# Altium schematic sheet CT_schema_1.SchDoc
size 542 x 264 mm
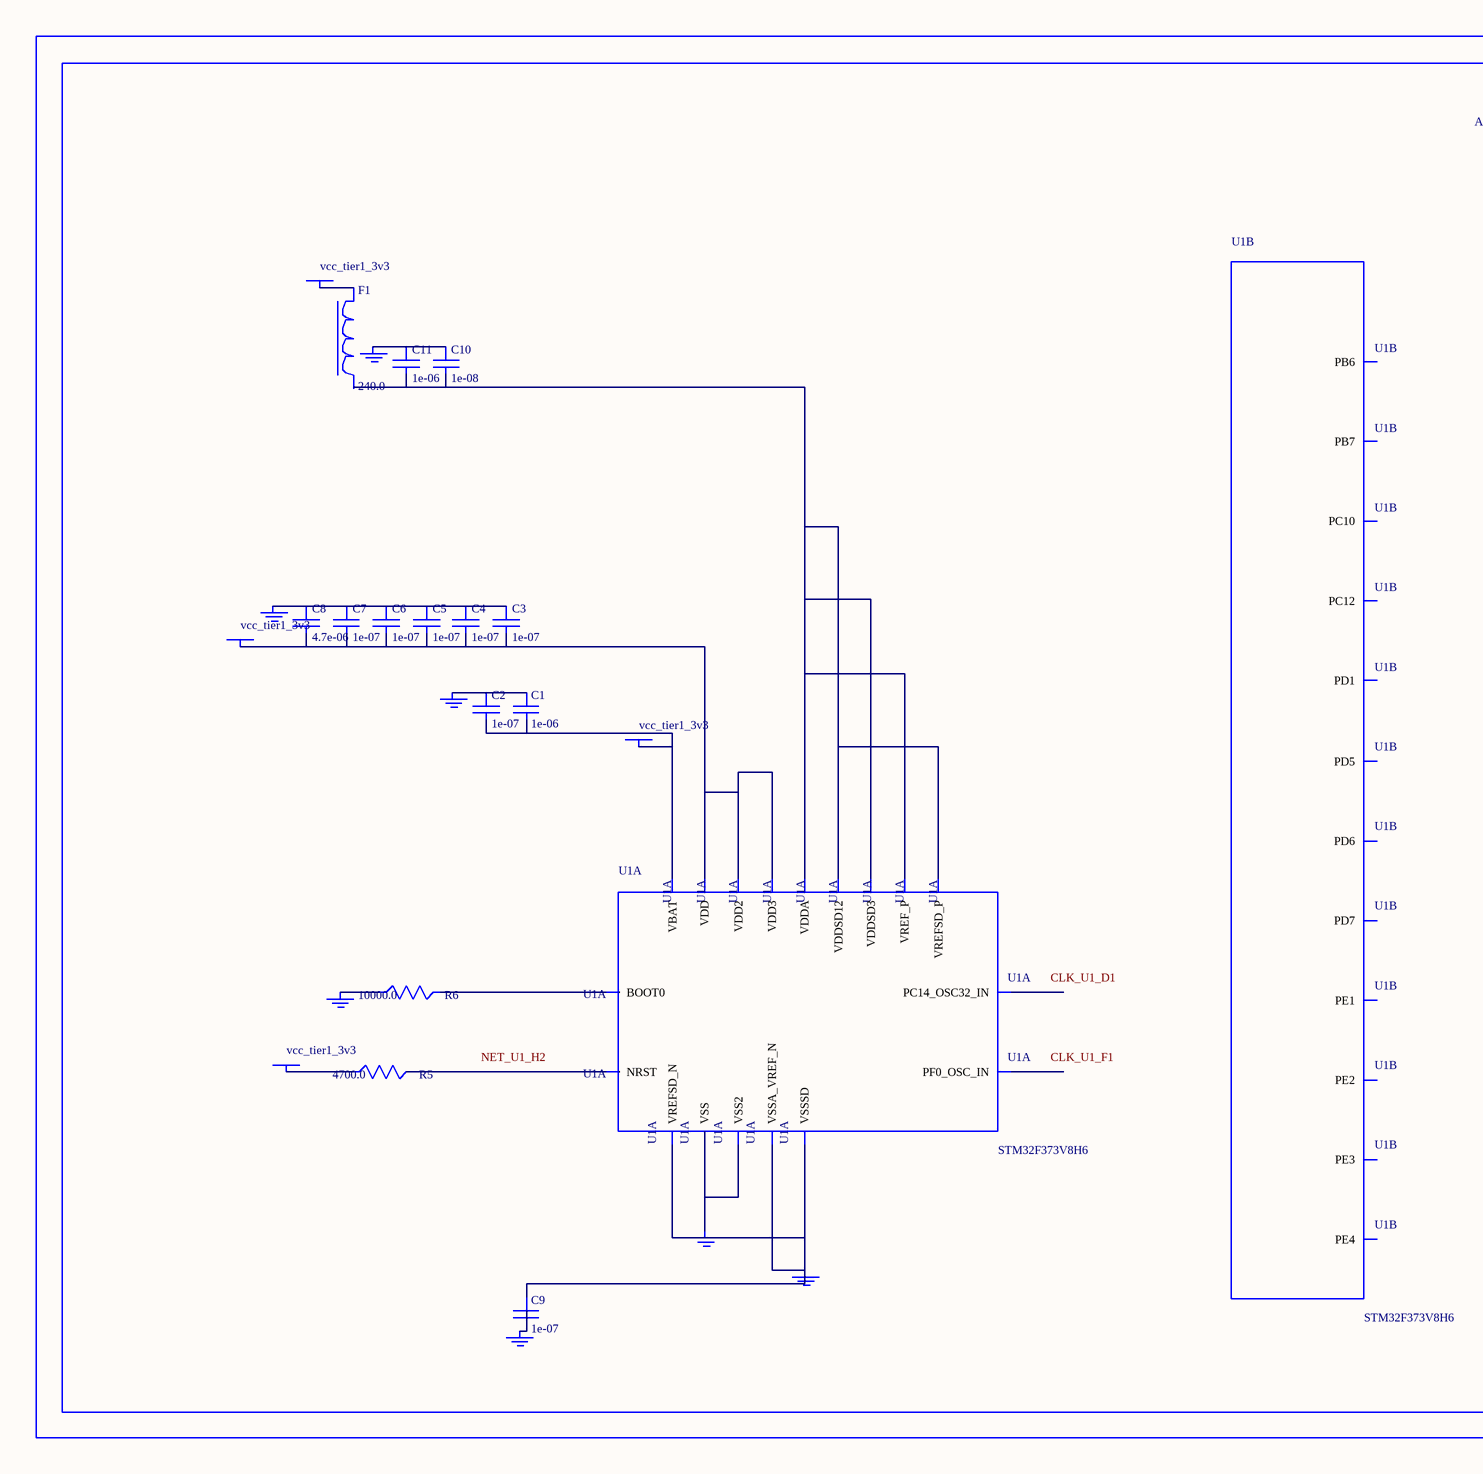
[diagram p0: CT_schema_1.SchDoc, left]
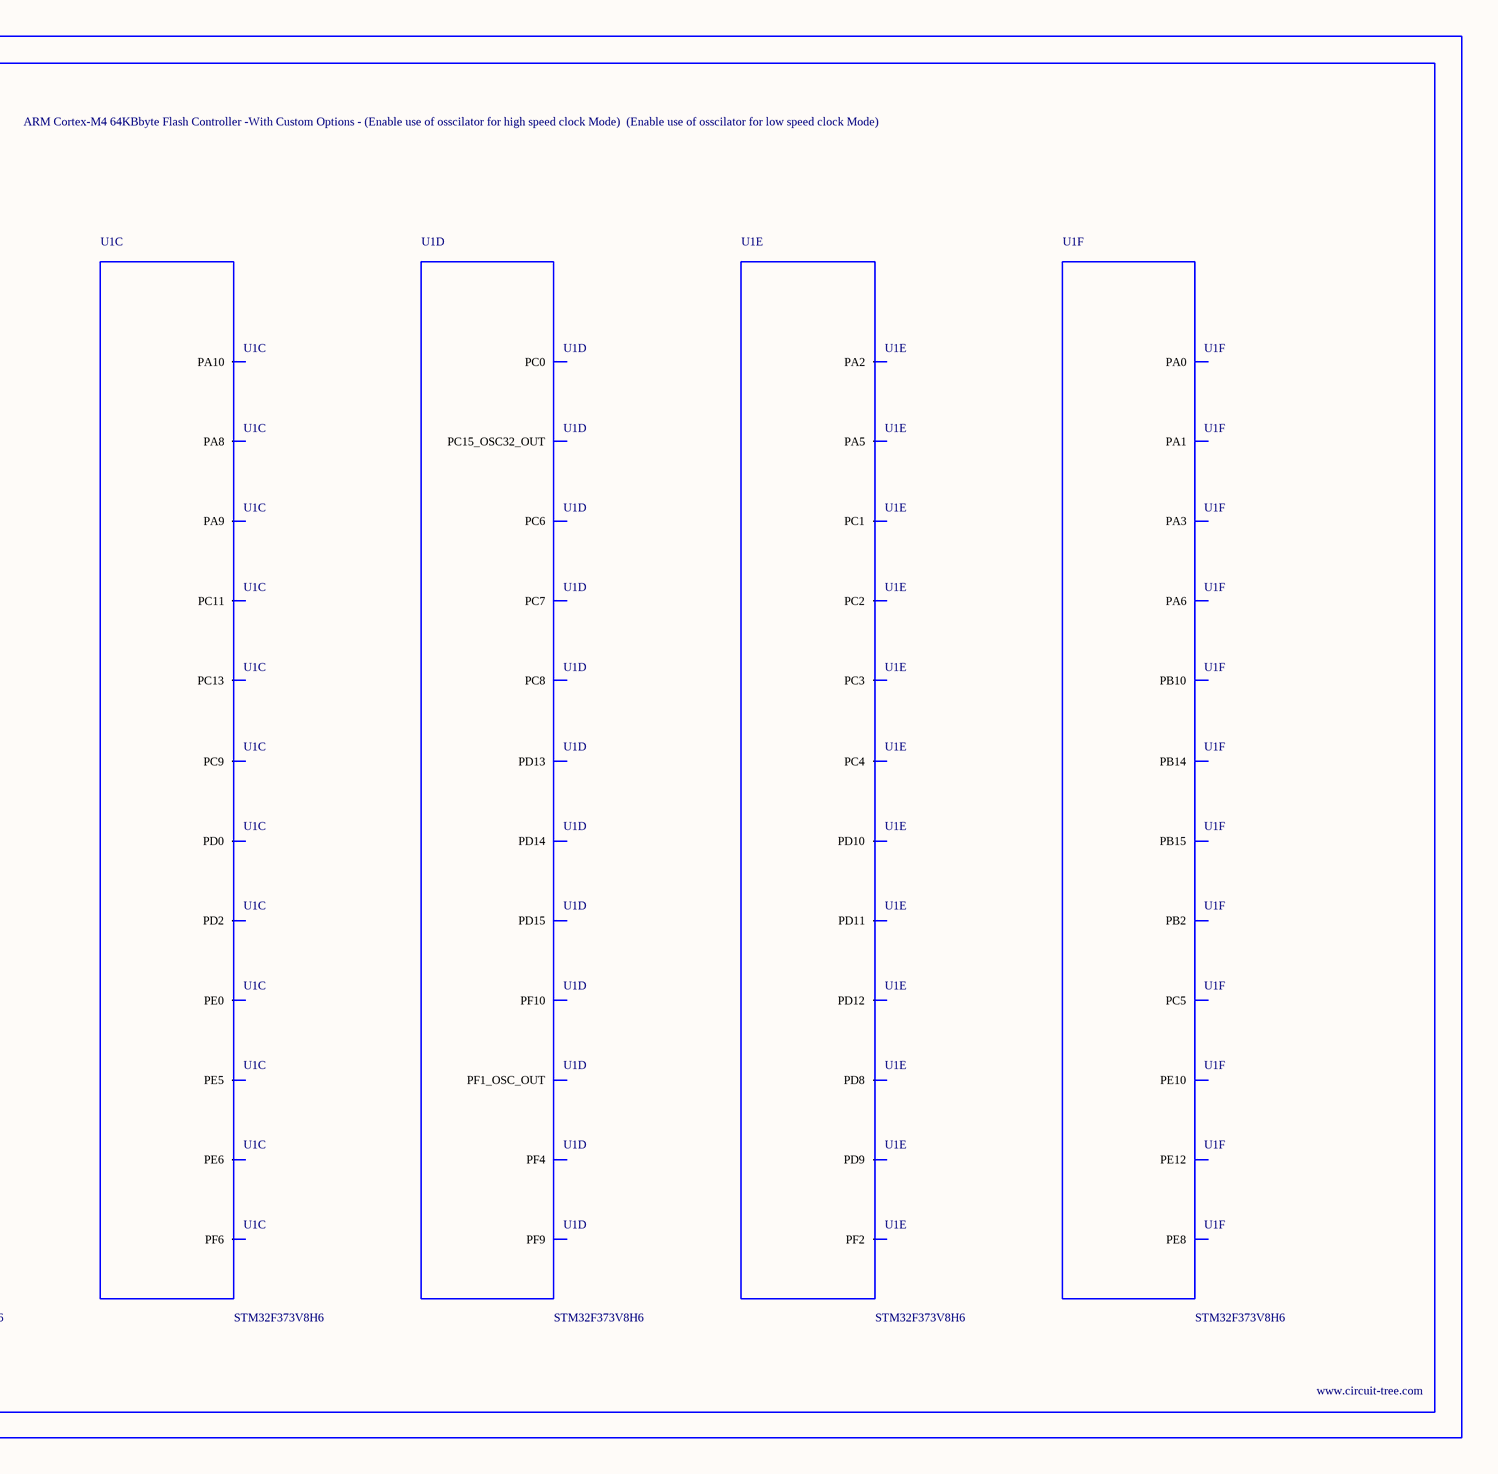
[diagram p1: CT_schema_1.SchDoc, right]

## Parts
BORDER0  (no value)
C1  1e-06  [C0603]
C2  1e-07  [C0603]
C3  1e-07  [C0603]
C4  1e-07  [C0603]
C5  1e-07  [C0603]
C6  1e-07  [C0603]
C7  1e-07  [C0603]
C8  4.7e-06  [C0603]
C9  1e-07  [C0603]
C10  1e-08  [C0603]
C11  1e-06  [C0603]
F1  240.0  [L0603]
GND_INSTANCE_0_0  (no value)
GND_INSTANCE_0_1  (no value)
GND_INSTANCE_0_2  (no value)
GND_INSTANCE_0_3  (no value)
GND_INSTANCE_0_4  (no value)
GND_INSTANCE_0_5  (no value)
GND_INSTANCE_0_6  (no value)
POWER_INSTANCE_0_0  vcc_tier1_3v3
POWER_INSTANCE_0_1  vcc_tier1_3v3
POWER_INSTANCE_0_2  vcc_tier1_3v3
POWER_INSTANCE_0_3  vcc_tier1_3v3
R5  4700.0  [R0603]
R6  10000.0  [R0603]
U1  STM32F373V8H6  [UFBGA100]  (parts A,B,C,D,E,F of 9)

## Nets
NetC1_1: C1.1 C2.1 GND_INSTANCE_0_0.0(GND)
NetC1_2: C1.2 C2.2 POWER_INSTANCE_0_0.0(PWR) U1.E2(VBAT)
NetC3_1: C3.1 C4.1 C5.1 C6.1 C7.1 C8.1 GND_INSTANCE_0_2.0(GND)
NetC3_2: C3.2 C4.2 C5.2 C6.2 C7.2 C8.2 POWER_INSTANCE_0_2.0(PWR) U1.C4(VDD) U1.G11(VDD2) U1.H3(VDD3)
NetC9_1: C9.1 GND_INSTANCE_0_5.0(GND) U1.F12(VSSSD) U1.K1(VSSA_VREF_N) U1.L11(VREFSD_N)
NetC9_2: C9.2 GND_INSTANCE_0_4.0(GND)
NetC10_1: C10.1 C11.1 GND_INSTANCE_0_1.0(GND)
NetC10_2: C10.2 C11.2 U1.G12(VDDSD12) U1.K12(VREFSD_P) U1.L1(VREF_P) U1.L12(VDDSD3) U1.M1(VDDA)
NetF1_1: F1.1 POWER_INSTANCE_0_1.0(PWR)
NetGND_INSTANCE_0_3_0: GND_INSTANCE_0_3.0(GND) R6.1
NetGND_INSTANCE_0_6_0: GND_INSTANCE_0_6.0(GND) U1.D3(VSS) U1.F11(VSS2)
NetPOWER_INSTANCE_0_3_0: POWER_INSTANCE_0_3.0(PWR) R5.1
NetR5_2: R5.2 U1.H2(NRST)
NetR6_2: R6.2 U1.A4(BOOT0)

Not connected (* = marked no-connect by the designer): F1 2; U1 A1(PE3) A2(PE1) A5(PD7) A6(PD5) B1(PE4) B2(PE2) B4(PB7) B5(PB6) B6(PD6) B9(PD1) B10(PC12) B11(PC10) C1(PC13) C2(PE5) C3(PE0) C8(PD2) C9(PD0) C10(PC11) C11(PF6) C12(PA10) D1(PC14_OSC32_IN) D2(PE6) D10(PA9) D11(PA8) D12(PC9) E1(PC15_OSC32_OUT) E3(PF4) E10(PC8) E11(PC7) E12(PC6) F1(PF0_OSC_IN) F2(PF9) G1(PF1_OSC_OUT) G2(PF10) H1(PC0) H10(PD15) H11(PD14) H12(PD13) J1(PF2) J2(PC1) J3(PC2) J10(PD12) J11(PD11) J12(PD10) K2(PC3) K3(PA2) K4(PA5) K5(PC4) K8(PD9) K9(PD8) K10(PB15) K11(PB14) L2(PA0) L3(PA3) L4(PA6) L5(PC5) L6(PB2) L7(PE8) L8(PE10) L9(PE12) L10(PB10) M2(PA1)

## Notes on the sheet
- Labels drawn without touching a wire or pin: CLK_U1_D1, CLK_U1_F1, NET_U1_H2

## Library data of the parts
BORDER0 = BORDER_PAGE0
C1 C11 = C0603C105K3RACTU
C2-C7 C9 = 06035C104K4Z2A
C8 = GRM188R6YA475KE15D
C10 = 06035C103K4Z2A
F1 = Z0603C241ASMST
GND_INSTANCE_0_0-GND_INSTANCE_0_6 = GND
POWER_INSTANCE_0_0-POWER_INSTANCE_0_3 = PWR
R5 = RC0603JR-074K7L
R6 = RC0603JR-0710KL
